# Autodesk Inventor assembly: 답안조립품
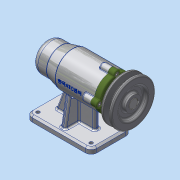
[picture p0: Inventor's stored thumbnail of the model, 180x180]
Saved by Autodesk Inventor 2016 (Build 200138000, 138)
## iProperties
Created: 2019-07
Part Number: 답안조립품
Document SubType Name: Assembly
Designer: MIRAE
Author: MIRAE
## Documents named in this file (12)
- C:\Users\MIRAE\Desktop\490704V1008\답안조립품.iam
- C:\Users\MIRAE\Desktop\490704V1008\본체.ipt
- C:\Users\MIRAE\Desktop\490704V1008\커버.ipt
- C:\Users\MIRAE\Desktop\490704V1008\베어링 6004.ipt
- C:\Users\MIRAE\Desktop\490704V1008\베어링 51202.ipt
- C:\Users\MIRAE\Desktop\490704V1008\어댑터슬리브.ipt
- C:\Users\MIRAE\Desktop\490704V1008\축.ipt
- C:\Users\MIRAE\Desktop\490704V1008\오일 실.ipt
- C:\Users\MIRAE\Desktop\490704V1008\볼트 M4.ipt
- C:\Users\MIRAE\Desktop\490704V1008\키 5 x 5 x 16.ipt
- C:\Users\MIRAE\Desktop\490704V1008\V벨트풀리.ipt
- C:\Users\MIRAE\Desktop\490704V1008\멈춤나사 M3.ipt
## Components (1 placed, 1 different names)
1. V벨트풀리:1
